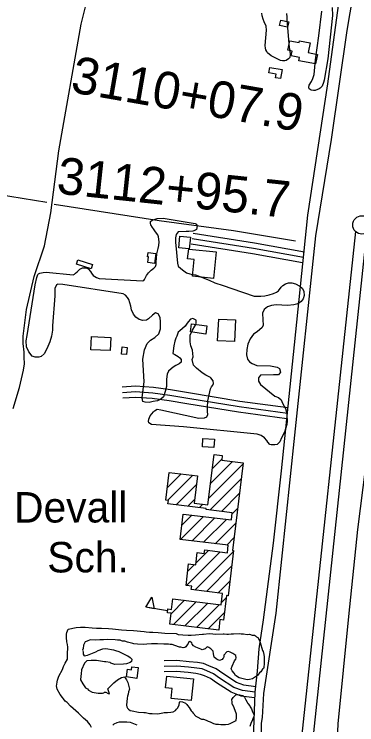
# Model space of a CAD drawing. Extents: x 3279314 to 3317160, y 734079 to 759431.
# Drawn here: x 3292879 to 3293812, y 741625 to 743558 of the extents above; entities that cross this region are included whole.
import ezdxf

# ---------------------------------------------------------------- set-up
doc = ezdxf.new("R2010")
doc.units = 0
for name, color, linetype in [('V-BLDG-OTLN', 7, 'Continuous'), ('V-DTCH-CNTR', 7, 'Continuous'), ('V-LEVE-TOET', 7, 'Continuous'), ('V-ROAD-CNTR', 7, 'Continuous'), ('V-SITE-VEGE', 7, 'Continuous'), ('V-SURV-IDEN', 7, 'Continuous'), ('V-SURV-LINE', 7, 'Continuous'), ('V-TOPO-SHOR', 7, 'Continuous')]:
    doc.layers.add(name, color=color, linetype=linetype)

msp = doc.modelspace()

# ---------------------------------------------------------------- linework, layer by layer
at = {"layer": 'V-BLDG-OTLN'}
for p, q in [((3293413.9, 742281.7), (3293473.5, 742341.4)), ((3293418.8, 742322), (3293444.6, 742347.8)), ((3293409.1, 742241.5), (3293501.6, 742334.1)), ((3293296.2, 742270), (3293333.8, 742307.7)), ((3293296.5, 742235), (3293365.4, 742303.9)), ((3293301, 742310.3), (3293302.3, 742311.5)), ((3293412.1, 742209.2), (3293496.8, 742293.9)), ((3293320.3, 742223.5), (3293375.6, 742278.8)), ((3293443.6, 742205.4), (3293491.9, 742253.7)), ((3293351.9, 742219.7), (3293370.7, 742238.6)), ((3293383.4, 742215.9), (3293392.2, 742224.6)), ((3293472.5, 742198.9), (3293487.1, 742213.5)), ((3293331.9, 742129), (3293394.2, 742191.3)), ((3293335.6, 742168.1), (3293362.7, 742195.1)), ((3293363.4, 742125.2), (3293425.7, 742187.5)), ((3293395, 742121.4), (3293457.3, 742183.7)), ((3293426.5, 742117.6), (3293482.2, 742173.3)), ((3293458.1, 742113.7), (3293477.4, 742133.1)), ((3293348.2, 742003.9), (3293439.6, 742095.3)), ((3293371, 741991.3), (3293476, 742096.4)), ((3293374.2, 742065.3), (3293408.1, 742099.1)), ((3293351.8, 742042.9), (3293369.7, 742060.8)), ((3293402.6, 741987.5), (3293471.2, 742056.2)), ((3293434.1, 741983.7), (3293466.3, 742016)), ((3293306.6, 741927), (3293343.1, 741963.5)), ((3293311.3, 741967), (3293311.6, 741967.3)), ((3293312.5, 741897.5), (3293374.7, 741959.7)), ((3293344.1, 741893.7), (3293406.2, 741955.8)), ((3293443.4, 741957.7), (3293456.3, 741970.5)), ((3293296.7, 741934.4), (3293237.6, 741944.4)), ((3293375.6, 741889.9), (3293437.8, 741952)), ((3293407.2, 741886.1), (3293451.4, 741930.3))]:
    msp.add_line(p, q, dxfattribs=at)
for points in [[(3293626.7, 743537.4), (3293623.3, 743522.9), (3293601.7, 743528), (3293605.1, 743542.5)], [(3293684.7, 743480.8), (3293679.5, 743453.7), (3293704.8, 743448.8), (3293699.8, 743422.9), (3293654.3, 743431.7), (3293656, 743440.4), (3293633.5, 743444.7), (3293636.1, 743458.2), (3293624.2, 743460.4), (3293629.2, 743486.3), (3293655.3, 743481.3), (3293656.2, 743486.3)], [(3293608.3, 743407.7), (3293603.9, 743383.3), (3293590.6, 743385.6), (3293592.3, 743395.3), (3293572.2, 743398.9), (3293574.8, 743413.6)], [(3293429.4, 742911.4), (3293421.9, 742839.4), (3293364.8, 742845.4), (3293369.5, 742890.7), (3293351.4, 742892.6), (3293354.3, 742920.2), (3293327.1, 742923), (3293330.4, 742954.5), (3293359.4, 742951.4), (3293356, 742919.1)], [(3293264.6, 742907.4), (3293261.2, 742880.3), (3293242.7, 742882.6), (3293244.6, 742897.9), (3293242.1, 742898.2), (3293243.6, 742910)], [(3293052.9, 742889.6), (3293092.3, 742877), (3293088.7, 742865.8), (3293049.3, 742878.4)], [(3293433.1, 742669.7), (3293435.9, 742728.7), (3293482.1, 742726.5), (3293479.4, 742667.6)], [(3293359, 742693.7), (3293362.2, 742715.9), (3293403.8, 742710), (3293400.7, 742687.9)], [(3293142.2, 742678.9), (3293140.7, 742643.2), (3293088.3, 742645.5), (3293089.9, 742681.2)], [(3293171.8, 742633.7), (3293173.6, 742652.9), (3293186.5, 742651.6), (3293184.6, 742632.4)], [(3293392.8, 742404.2), (3293424.3, 742402.2), (3293422.9, 742379.5), (3293391.4, 742381.4)], [(3293442.6, 741951.4), (3293446.4, 741982.3), (3293361.2, 741992.5), (3293362.4, 742002.2), (3293347.2, 742004), (3293354.2, 742062.6), (3293373.6, 742060.3), (3293377.6, 742093.4), (3293396.7, 742091.1), (3293397.8, 742100.4), (3293459.6, 742092.9), (3293462.1, 742113.3), (3293330.9, 742129.1), (3293339.2, 742198), (3293470.5, 742182.1), (3293472.9, 742201.9), (3293401.7, 742210.5), (3293402.1, 742213.6), (3293297.9, 742226.2), (3293298.9, 742234.7), (3293292, 742235.6), (3293301.2, 742311.7), (3293378.4, 742302.3), (3293369.4, 742227.4), (3293406.8, 742222.9), (3293423.4, 742360.1), (3293445.7, 742357.4), (3293444.2, 742344.9), (3293502.1, 742337.9), (3293473.3, 742099), (3293476.3, 742098.6), (3293461.5, 741976), (3293457, 741976.6), (3293448.9, 741909.7), (3293439.4, 741910.8), (3293436, 741882.6), (3293303.2, 741898.6), (3293306.8, 741928.4), (3293296.2, 741929.7), (3293297.4, 741939.9), (3293307.9, 741938.6), (3293311.4, 741967.3)], [(3293237.6, 741944.4), (3293253.9, 741972.1), (3293260.3, 741940.6)], [(3293213.3, 741751.1), (3293185.3, 741754.8), (3293188.1, 741775.9), (3293198.2, 741774.5), (3293199.3, 741782.8), (3293217.2, 741780.5)], [(3293361.3, 741690.6), (3293306.4, 741696.3), (3293309.2, 741723.2), (3293291.4, 741725.1), (3293294.7, 741757), (3293367.3, 741749.5)]]:
    msp.add_lwpolyline(points, close=True, dxfattribs=at)
at = {"layer": 'V-DTCH-CNTR'}
msp.add_lwpolyline([(3292876.7, 742485.5), (3292893.6, 742542.7), (3292904.7, 742589.8), (3292907.6, 742607.2), (3292906.4, 742624.7), (3292906.1, 742639), (3292903.5, 742662.7), (3292903.8, 742682.2), (3292912.8, 742755), (3292933.5, 742844.5), (3292961.7, 742928.2), (3292979.2, 743017.8), (3293001.2, 743186.4), (3293061.4, 743531.4), (3293082.9, 743615.3), (3293102, 743646.2), (3293125.6, 743676.6), (3293147.6, 743701.4), (3293160.3, 743717.6), (3293164, 743726.8), (3293169.4, 743741.6), (3293171.7, 743758.6)], dxfattribs=at)
at = {"layer": 'V-LEVE-TOET'}
for points in [[(3293809.1, 743659.5), (3293784.9, 743513.9), (3293742.3, 743217.7), (3293699.8, 742955.4), (3293642.3, 742412.7), (3293606.6, 742075.4), (3293591.8, 741928.1), (3293557.9, 741709.6), (3293553.8, 741644.4), (3293551.7, 741629.6), (3293550.3, 741439.8), (3293540.9, 741286.6), (3293521.5, 741171.5)], [(3293739.6, 741115), (3293761.4, 741627.1), (3293790.1, 741919.3), (3293814.8, 742155.9), (3293849.9, 742434.4), (3293883.8, 742730.5), (3293906.9, 742907.4), (3293950.6, 743164), (3293992.4, 743447.1), (3294019.4, 743591.8)]]:
    msp.add_lwpolyline(points, dxfattribs=at)
at = {"layer": 'V-ROAD-CNTR'}
for points in [[(3293528.9, 741526.8), (3293531.6, 741611), (3293535.4, 741713.4), (3293541.9, 741770.8), (3293546.3, 741831.1), (3293557.9, 741910.4), (3293585.1, 742118.9), (3293606.9, 742315.5), (3293648.2, 742720.4), (3293678.2, 743011.9), (3293732.9, 743368.5), (3293770.3, 743642.6)], [(3293366, 742962.7), (3293533.1, 742936.6), (3293669.1, 742912.1)], [(3293363.7, 742947.9), (3293530.7, 742921.8), (3293666.4, 742897.3)], [(3293363.7, 742947.9), (3293530.7, 742921.8), (3293666.4, 742897.3)], [(3293361.4, 742933.1), (3293528.2, 742907), (3293663.7, 742882.6)], [(3293172.9, 742544.3), (3293209.2, 742546.7), (3293258.5, 742543.2), (3293305.1, 742536.7), (3293353.9, 742528.7), (3293493.8, 742505.6), (3293625, 742487.7)], [(3293173.9, 742529.3), (3293209.1, 742531.7), (3293256.9, 742528.3), (3293302.9, 742521.8), (3293351.5, 742513.9), (3293491.6, 742490.8), (3293623, 742472.8)], [(3293173.9, 742529.3), (3293209.1, 742531.7), (3293256.9, 742528.3), (3293302.9, 742521.8), (3293351.5, 742513.9), (3293491.6, 742490.8), (3293623, 742472.8)], [(3293174.9, 742514.4), (3293209.1, 742516.6), (3293255.3, 742513.3), (3293300.7, 742507), (3293349.1, 742499.1), (3293489.4, 742476), (3293621, 742457.9)], [(3293537.2, 741728.3), (3293504.2, 741732.3), (3293484, 741740.1), (3293446.8, 741764.2), (3293428.8, 741776.9), (3293409.2, 741785.6), (3293394.7, 741791.1), (3293378, 741793.9), (3293355.6, 741796.5), (3293322.3, 741799.4), (3293287.4, 741798.8)], [(3293535.4, 741713.4), (3293500.6, 741717.7), (3293477.1, 741726.6), (3293438.4, 741751.8), (3293421.4, 741763.8), (3293403.4, 741771.8), (3293390.8, 741776.6), (3293376, 741779), (3293354.1, 741781.6), (3293321.8, 741784.4), (3293287.7, 741783.8)], [(3293535.4, 741713.4), (3293500.6, 741717.7), (3293477.1, 741726.6), (3293438.4, 741751.8), (3293421.4, 741763.8), (3293403.4, 741771.8), (3293390.8, 741776.6), (3293376, 741779), (3293354.1, 741781.6), (3293321.8, 741784.4), (3293287.7, 741783.8)], [(3293533.6, 741698.5), (3293496.9, 741703), (3293470.3, 741713.2), (3293430, 741739.3), (3293413.9, 741750.7), (3293397.7, 741757.9), (3293386.8, 741762), (3293373.9, 741764.2), (3293352.6, 741766.6), (3293321.3, 741769.4), (3293287.9, 741768.8)]]:
    msp.add_lwpolyline(points, dxfattribs=at)
at = {"layer": 'V-SITE-VEGE'}
for points in [[(3293620.7, 743560.6), (3293621.8, 743550.3), (3293621.5, 743542.4), (3293622.4, 743531.8), (3293627.4, 743467.9), (3293629.9, 743459.5), (3293630.3, 743447.4), (3293629.3, 743440.9), (3293626.1, 743436.7), (3293619.7, 743432.3), (3293615.7, 743431.7), (3293610, 743431.8), (3293604.1, 743432.3), (3293579.1, 743445.3), (3293569.2, 743452.9), (3293566.6, 743456.9), (3293564.5, 743461.1), (3293563.7, 743465.7), (3293562.7, 743473.2), (3293565.9, 743515.1), (3293565, 743525.8), (3293559.7, 743537.6), (3293557.2, 743545.1), (3293554.5, 743553.7), (3293553.3, 743561.6)], [(3293744.8, 743577), (3293745.5, 743555.1), (3293733, 743437.2), (3293723.2, 743378.6), (3293721.6, 743372.3), (3293717.4, 743362.2), (3293712.5, 743357.3), (3293709.8, 743355.6), (3293698.1, 743351), (3293693.7, 743350.8), (3293687.6, 743352), (3293682.4, 743355.6), (3293680.9, 743358.7), (3293682.4, 743365.5), (3293688.9, 743375.5), (3293692.3, 743383.5), (3293695.4, 743394.5), (3293699.8, 743434.5), (3293708.5, 743499.3), (3293716.9, 743566.6)], [(3293285.7, 742517.4), (3293278.4, 742510.7), (3293269.5, 742506.7), (3293257.8, 742504.3), (3293246.6, 742501.4), (3293235.6, 742502.3), (3293229.8, 742504.8), (3293227.9, 742514.3), (3293229.1, 742530), (3293232.7, 742558.1), (3293230.2, 742604), (3293229.8, 742619.8), (3293233.8, 742645.4), (3293241.6, 742662.4), (3293250.1, 742671.7), (3293261.8, 742678.7), (3293272.6, 742688.6), (3293277.2, 742702.6), (3293277.5, 742720.8), (3293276.6, 742733.3), (3293271.1, 742742.8), (3293263.5, 742745.4), (3293256.1, 742739.8), (3293244.8, 742729.7), (3293239.4, 742726.1), (3293229.1, 742724.9), (3293219.7, 742727.5), (3293210.2, 742734), (3293204.4, 742742), (3293198.2, 742754.2), (3293196.9, 742763.9), (3293191.3, 742781.6), (3293188.1, 742787.3), (3293182.5, 742793.4), (3293175.5, 742797), (3293011.6, 742822.5), (3292997.8, 742823.9), (3292994.3, 742821.5), (3292989.9, 742812.2), (3292989.5, 742803.4), (3292990.2, 742791.8), (3292983.5, 742710.5), (3292983.5, 742698.4), (3292981.2, 742682.2), (3292975.9, 742667.1), (3292971.1, 742653.8), (3292965.6, 742641.9), (3292960.8, 742634.5), (3292953, 742627.2), (3292946.2, 742624.7), (3292936.1, 742625.1), (3292928.2, 742628.1), (3292919.2, 742639.4), (3292913.1, 742653.1), (3292912.3, 742669.4), (3292914.3, 742683.8), (3292936.8, 742821.5), (3292940.9, 742842), (3292943.8, 742849.7), (3292945.4, 742851.8), (3292949, 742853.5), (3292958.2, 742855.3), (3292966.6, 742856), (3293040.2, 742848.8), (3293043.5, 742851.4), (3293046.4, 742854), (3293051.1, 742857.6), (3293057.6, 742864.5), (3293065.1, 742868.5), (3293075.2, 742868.4), (3293080.6, 742865.2), (3293086.6, 742858.1), (3293089.4, 742853.4), (3293094.4, 742847.6), (3293103.3, 742842), (3293110.9, 742839.6), (3293229.7, 742832.4), (3293232.1, 742833.7), (3293234.4, 742836.5), (3293239.4, 742847.4), (3293245, 742855), (3293251.7, 742861.7), (3293259.5, 742867.5), (3293264, 742871.8), (3293265.8, 742877.2), (3293266, 742885.1), (3293266.8, 742893.9), (3293267.2, 742906.2), (3293271.5, 742920.8), (3293273.1, 742928.7), (3293273.8, 742939.2), (3293272.5, 742952.6), (3293269.9, 742958.4), (3293263.9, 742966.4), (3293258.4, 742974.1), (3293255.6, 742977.7), (3293250.9, 742985), (3293250.1, 742989), (3293250.6, 742994), (3293254.6, 742997.9), (3293268.8, 743002.7)], [(3293268.8, 743002.7), (3293284.4, 743003.5), (3293372.3, 742988.8), (3293375.1, 742987), (3293377, 742982.8), (3293375.5, 742972.9), (3293372.9, 742970.3), (3293365.6, 742967.8), (3293355, 742966.7), (3293347.1, 742966.8), (3293325.6, 742965.9), (3293320, 742958.6), (3293318.3, 742949.8), (3293318.1, 742937.3), (3293319, 742929.4), (3293323.6, 742881.2), (3293325.5, 742872.9), (3293333.2, 742866.1), (3293340.8, 742860.1), (3293348.4, 742854.9), (3293357.6, 742851.7), (3293364.6, 742850), (3293372.4, 742848.8), (3293409.7, 742834.9), (3293425.2, 742827.6), (3293447.9, 742820.4), (3293471.8, 742811.6), (3293532.5, 742791.5), (3293539.1, 742791.1), (3293550.7, 742791.3), (3293561.3, 742792.3), (3293572.9, 742794.7), (3293585.3, 742798.4), (3293593, 742801.8), (3293598.6, 742805.6), (3293606.2, 742815.6), (3293610.7, 742820.1), (3293618.2, 742824.4), (3293626.2, 742827.1), (3293635.2, 742827.6), (3293644.8, 742825), (3293657.2, 742818.4), (3293663.7, 742811.9), (3293667.7, 742804.2), (3293668.6, 742792.5), (3293665.8, 742783.4), (3293660.8, 742776.4), (3293651.3, 742770.5), (3293640.7, 742767.6), (3293622.9, 742765.3), (3293592.4, 742767.6), (3293580.1, 742765.6), (3293568.8, 742761.8), (3293560.1, 742754.5), (3293555.1, 742745), (3293556.3, 742726.7), (3293556.7, 742711.8), (3293554.2, 742705.7), (3293540.6, 742694.1), (3293530.4, 742687.3), (3293521.4, 742675.1), (3293515.2, 742660.8), (3293512.3, 742646.1), (3293511.6, 742631.4), (3293514.5, 742619.9), (3293519.6, 742612.6), (3293527, 742608.1), (3293539.9, 742602.8)], [(3293539.9, 742602.8), (3293576.5, 742601.9), (3293595.5, 742597.6), (3293601.6, 742594.7), (3293603.8, 742583.9), (3293598.9, 742577.4), (3293585.3, 742577.2), (3293549.3, 742576.3), (3293544.5, 742568.7), (3293544.1, 742559.7), (3293550.1, 742550.6), (3293589, 742519), (3293598.4, 742515.1), (3293606.2, 742508.6), (3293610, 742499.7), (3293618.1, 742485.7), (3293620.5, 742475.6), (3293621.5, 742466.4), (3293622.5, 742451.7), (3293621.5, 742441.8), (3293619.1, 742432.6), (3293614.7, 742421.3), (3293606.5, 742405.4), (3293602, 742394.7), (3293595, 742387.6), (3293589.1, 742386.6), (3293578.8, 742386.2), (3293574.8, 742387.8), (3293569.7, 742393.8), (3293566.5, 742398.5), (3293560.7, 742405.6), (3293551.3, 742411.9), (3293540.2, 742416), (3293340, 742435.2), (3293253, 742442), (3293246, 742446.3), (3293245.2, 742449.9), (3293246.2, 742456), (3293249.7, 742465.2), (3293254.4, 742471.2), (3293258.6, 742476), (3293260.9, 742479.4), (3293268.2, 742483.5), (3293278.5, 742482), (3293381.5, 742459.3), (3293397.3, 742459.9), (3293403.5, 742462.8), (3293406.2, 742468.7), (3293405.9, 742477.7), (3293405.5, 742487.8), (3293406, 742506.7), (3293413.6, 742539.2), (3293416.8, 742544.4), (3293419.9, 742549.2), (3293422, 742553.1), (3293420.8, 742560.8), (3293414.6, 742568.8), (3293413.3, 742569.8), (3293401.1, 742576.3), (3293390.7, 742582.7), (3293375.6, 742595.2), (3293367.4, 742603.7), (3293363.9, 742618.7), (3293366.5, 742626.3), (3293365.7, 742634.7), (3293364.6, 742643.7), (3293360.2, 742656.1), (3293358, 742666.9), (3293357.9, 742684.6), (3293364.7, 742698.3), (3293370.6, 742709.2), (3293373.5, 742713.8), (3293374.7, 742717.5), (3293374.8, 742725.6), (3293365.5, 742730.4), (3293359.5, 742728.5), (3293352.6, 742721.4), (3293348.3, 742715.3), (3293344.7, 742709.9), (3293330, 742696.3), (3293325.3, 742692.7), (3293321.8, 742681.8), (3293319.5, 742676.8), (3293316.8, 742668.9), (3293313.4, 742655.6), (3293310.7, 742635.2), (3293316.3, 742632.3), (3293325.4, 742627.3), (3293330.4, 742623.7), (3293333.8, 742618.6), (3293333.9, 742611.6), (3293327.9, 742607.1), (3293319.5, 742602.4), (3293312.4, 742597.7), (3293306.8, 742593.4), (3293299.7, 742586.9), (3293295.8, 742578.9), (3293294.3, 742565.3), (3293293.5, 742545.3), (3293290.6, 742532), (3293285.7, 742517.4)], [(3292996.7, 741721.8), (3292994.4, 741731.1), (3292995, 741734.1), (3292996.4, 741741.5), (3292997.1, 741745.8), (3293001, 741757.4), (3293010.5, 741775), (3293013.7, 741783), (3293015, 741786.6), (3293018.2, 741792.1), (3293024, 741803.7), (3293024.3, 741822.1), (3293025.1, 741830.7), (3293025.1, 741835.6), (3293024.7, 741843), (3293022.9, 741850.4), (3293021.9, 741862.7), (3293021.4, 741865.2), (3293022.1, 741871.3), (3293022.2, 741875.7), (3293026.6, 741884.8), (3293047.6, 741889.3), (3293059.9, 741890.3), (3293072.8, 741890.1), (3293091.9, 741888.5), (3293103.5, 741887.7), (3293117.1, 741888.1), (3293136.1, 741887.1), (3293147.2, 741885.7), (3293171.7, 741882.8), (3293184.6, 741882), (3293204.3, 741881), (3293233.1, 741878.6), (3293238.6, 741877.3), (3293247.2, 741876.5), (3293256.4, 741876.4), (3293271.2, 741875.5), (3293289, 741873.9), (3293320.3, 741872.8), (3293325.8, 741870.8), (3293338.1, 741869.4), (3293352.8, 741868.5), (3293361.4, 741868.9), (3293372.5, 741869.4), (3293391.6, 741870.9), (3293394.7, 741871.4), (3293410.1, 741873), (3293419.9, 741872.2), (3293428.5, 741871.4), (3293448.2, 741872.3), (3293450.6, 741872.3), (3293458, 741871.5), (3293462.9, 741871.4), (3293470.3, 741872.5), (3293475.8, 741872.4), (3293491.2, 741872.8), (3293496.7, 741872), (3293503.5, 741871.9), (3293513.3, 741870.5), (3293519.5, 741871), (3293527.4, 741869), (3293533.6, 741868.3), (3293536, 741867), (3293539, 741863.9), (3293542.1, 741862), (3293546.2, 741855.8), (3293549.2, 741848.4), (3293555.6, 741827.3), (3293557.4, 741824.2), (3293558.4, 741815.6), (3293559.6, 741810.1), (3293560, 741802.1), (3293559.9, 741792.8), (3293559, 741779.9), (3293557.8, 741778.1), (3293555.3, 741775.7), (3293550.2, 741769), (3293547.1, 741766), (3293541.4, 741758.7), (3293527.7, 741749.8), (3293519.7, 741748.1), (3293514.8, 741747.5), (3293509.9, 741747.6), (3293492.1, 741752.2), (3293481.8, 741759.2), (3293477.6, 741765.4), (3293472.8, 741771.7), (3293469.8, 741776.6), (3293472.4, 741784.6), (3293478.8, 741799.2), (3293482.6, 741803.4), (3293483.3, 741807.1), (3293482.8, 741813.3), (3293474.3, 741818.4), (3293466.9, 741822.2), (3293462.7, 741824.1), (3293458.4, 741823.6), (3293450.2, 741813.9), (3293450.1, 741810.8), (3293448.8, 741807.1), (3293447.6, 741804.7)], [(3293447.6, 741804.7), (3293445.1, 741802.3), (3293438.2, 741799.3), (3293431.5, 741802.5), (3293429.1, 741803.8), (3293423.7, 741808.8), (3293422, 741817.4), (3293420.9, 741824.8), (3293414.8, 741831.1), (3293409.4, 741834.9), (3293405.1, 741836.8), (3293403.2, 741835.6), (3293398.9, 741831.4), (3293390.8, 741829.1), (3293387.2, 741830.4), (3293382.9, 741832.3), (3293373.7, 741836.1), (3293367, 741839.3), (3293364.1, 741844.3), (3293362.9, 741847.4), (3293360.5, 741849.9), (3293357.4, 741851.2), (3293354.9, 741850.6), (3293352.4, 741845.7), (3293350.5, 741842.7), (3293346.7, 741837.2), (3293343.6, 741835.5), (3293339.3, 741834.3), (3293333.2, 741835.6), (3293328.9, 741836.3), (3293316.6, 741840.2), (3293309.3, 741842.8), (3293303.8, 741843.5), (3293299.5, 741844.2), (3293286.6, 741844.5), (3293269.4, 741845.4), (3293266.3, 741845.4), (3293258.9, 741845), (3293252.8, 741845.1), (3293239.9, 741844.1), (3293232.5, 741843), (3293215.3, 741843.9), (3293205.4, 741844.7), (3293202.4, 741846), (3293187.7, 741849.3), (3293180.4, 741852.5), (3293174.2, 741852.6), (3293171.2, 741853.3), (3293168.1, 741854.6), (3293160.8, 741855.3), (3293154, 741855.5), (3293133.1, 741856.4), (3293122.6, 741856), (3293112.2, 741856.2), (3293101.7, 741855.2), (3293085.7, 741855.5), (3293077.7, 741852.5), (3293072.7, 741850.2), (3293070.8, 741847.1), (3293068.3, 741841), (3293066.9, 741832.4), (3293065.6, 741828.1), (3293066.2, 741825.7), (3293066.7, 741822), (3293067.2, 741817.1), (3293070.2, 741812.7), (3293078.9, 741813.8), (3293101.2, 741823.2), (3293108, 741826.8), (3293121, 741831.5), (3293128.4, 741831.9), (3293149.2, 741828.5), (3293154.7, 741827.2), (3293163.9, 741823.9), (3293185.8, 741813.7), (3293188.9, 741812.4), (3293194.9, 741808), (3293199.2, 741803), (3293198.4, 741796.9), (3293195.3, 741793.8), (3293185.4, 741790.3), (3293176.8, 741789.9), (3293152.8, 741789.1), (3293150.4, 741789.7), (3293142.4, 741792.3), (3293140.6, 741794.2), (3293128.9, 741795.7), (3293125.3, 741796.3), (3293103.8, 741799.8), (3293096.4, 741799.3), (3293088.4, 741800.1), (3293077.3, 741798.4), (3293074.9, 741796.6), (3293070.5, 741792.4), (3293062.8, 741774.1), (3293061.4, 741763.7), (3293060.6, 741756.9), (3293059.8, 741747.1), (3293065.8, 741735.9), (3293073.6, 741725.3), (3293075.4, 741724.1)], [(3293075.4, 741724.1), (3293079.1, 741722.2), (3293081.5, 741719), (3293091.2, 741713.9), (3293107.8, 741711.2), (3293110.8, 741710.5), (3293115.7, 741710.4), (3293119.4, 741711), (3293123.1, 741712.1), (3293125, 741713.3), (3293128.7, 741713.3), (3293134.8, 741710.1), (3293139.1, 741708.8), (3293136.1, 741717.4), (3293133.8, 741722.4), (3293136.3, 741724.2), (3293143.8, 741732.7), (3293150.1, 741738.7), (3293160.7, 741747.1), (3293171.8, 741753.7), (3293176.2, 741754.2), (3293179.2, 741754.8), (3293184.6, 741747.3), (3293188.8, 741739.9), (3293192.8, 741721.3), (3293190.8, 741714), (3293189.5, 741707.9), (3293188.1, 741702.4), (3293186.8, 741697.5), (3293185.2, 741677.8), (3293185.8, 741673.5), (3293187.6, 741670.4), (3293190.6, 741667.3), (3293195.4, 741663.5), (3293200.3, 741662.8), (3293218.1, 741659.4), (3293232.2, 741658.5), (3293237.1, 741657.8), (3293247.5, 741655.8), (3293254.9, 741655.7), (3293270.3, 741654.2), (3293283.8, 741657), (3293287.6, 741658.2), (3293296.8, 741658), (3293305.4, 741659.1), (3293311.6, 741660.2), (3293318.4, 741663.8), (3293320.9, 741667.4), (3293324, 741670.4), (3293327.9, 741678.3), (3293329.2, 741686.3), (3293331.1, 741688.1), (3293337.3, 741687.4), (3293345.8, 741683.6), (3293349.4, 741680.4), (3293351.2, 741677.3), (3293355.4, 741671.7), (3293361.4, 741663), (3293363.8, 741659.9), (3293366.2, 741656.1), (3293374.1, 741648), (3293377.1, 741646.1), (3293389.3, 741640.4), (3293394.8, 741639.6), (3293402.1, 741637.1), (3293407.6, 741634.5), (3293412.5, 741632.6), (3293421.7, 741628.7), (3293425.3, 741627.4), (3293428.4, 741626.7), (3293435.8, 741626), (3293441.3, 741625.9), (3293446.2, 741625.8), (3293452.4, 741625.7), (3293454.8, 741625.7), (3293462.2, 741626.7), (3293467.1, 741627.9), (3293483.3, 741636.8), (3293484, 741644.2), (3293484.2, 741654), (3293478.4, 741670.7), (3293474.2, 741678.8), (3293473, 741680.7), (3293472.4, 741683.1), (3293472.5, 741686.2), (3293472, 741693.6), (3293475.2, 741699.1), (3293483.3, 741706.9), (3293487.6, 741707.4), (3293493.2, 741706.7), (3293501.7, 741704.7), (3293506.6, 741700.3), (3293510.1, 741692.9), (3293513.1, 741686.1), (3293515.5, 741682.4), (3293520.9, 741676.1), (3293521.5, 741673.6), (3293525, 741668), (3293528, 741660), (3293532.1, 741650.7), (3293531.4, 741647.6)], [(3293089.5, 741617.5), (3293085.9, 741624.9), (3293078.7, 741633.6), (3293067.8, 741643.1), (3293054.5, 741656.8), (3293032.7, 741675.7), (3293023.1, 741685), (3293018.2, 741688.8), (3293013.4, 741695.1), (3293010.4, 741699.4), (3293004.4, 741706.9), (3292996.7, 741721.8)], [(3293531.4, 741647.6), (3293530.1, 741643.4), (3293527.6, 741637.9), (3293523.7, 741628.7), (3293521.1, 741620.2)], [(3293214.4, 741623.8), (3293195.5, 741630.9), (3293185.6, 741631.7), (3293176.4, 741631.9), (3293165.3, 741631.5), (3293158.6, 741630.4), (3293150.5, 741626.2), (3293147.4, 741623.8)]]:
    msp.add_lwpolyline(points, dxfattribs=at)
at = {"layer": 'V-SURV-LINE'}
for points in [[(3293659.8, 741564.5), (3293808.8, 742966.7)], [(3293838.6, 742963.6), (3293689.6, 741561.3)]]:
    msp.add_lwpolyline(points, dxfattribs=at)
msp.add_circle((3293825.8, 742985), 25, dxfattribs=at)
at = {"layer": 'V-TOPO-SHOR'}
msp.add_line((3291400.2, 743290.8), (3292968.1, 743047.3), dxfattribs=at)
msp.add_lwpolyline([(3292987.7, 743041.7), (3293274.3, 742997.4), (3293476.6, 742969.8), (3293645.2, 742942.1)], dxfattribs=at)

# ---------------------------------------------------------------- texts
at = {"layer": 'V-BLDG-OTLN'}
for s, p in [('Devall', (3292879.1, 742174.8)), ('Sch.', (3292969.4, 742039.2))]:
    msp.add_text(s, height=83, rotation=0.1349, dxfattribs=at).set_placement(p)
at = {"layer": 'V-SURV-IDEN'}
for s, rotation, p in [('3110+07.9', 350.1464, (3293030, 743346.8)), ('3112+95.7', 353.9139, (3292992.5, 743070.8))]:
    msp.add_text(s, height=100, rotation=rotation, dxfattribs=at).set_placement(p)

doc.saveas('drawing.dxf')
